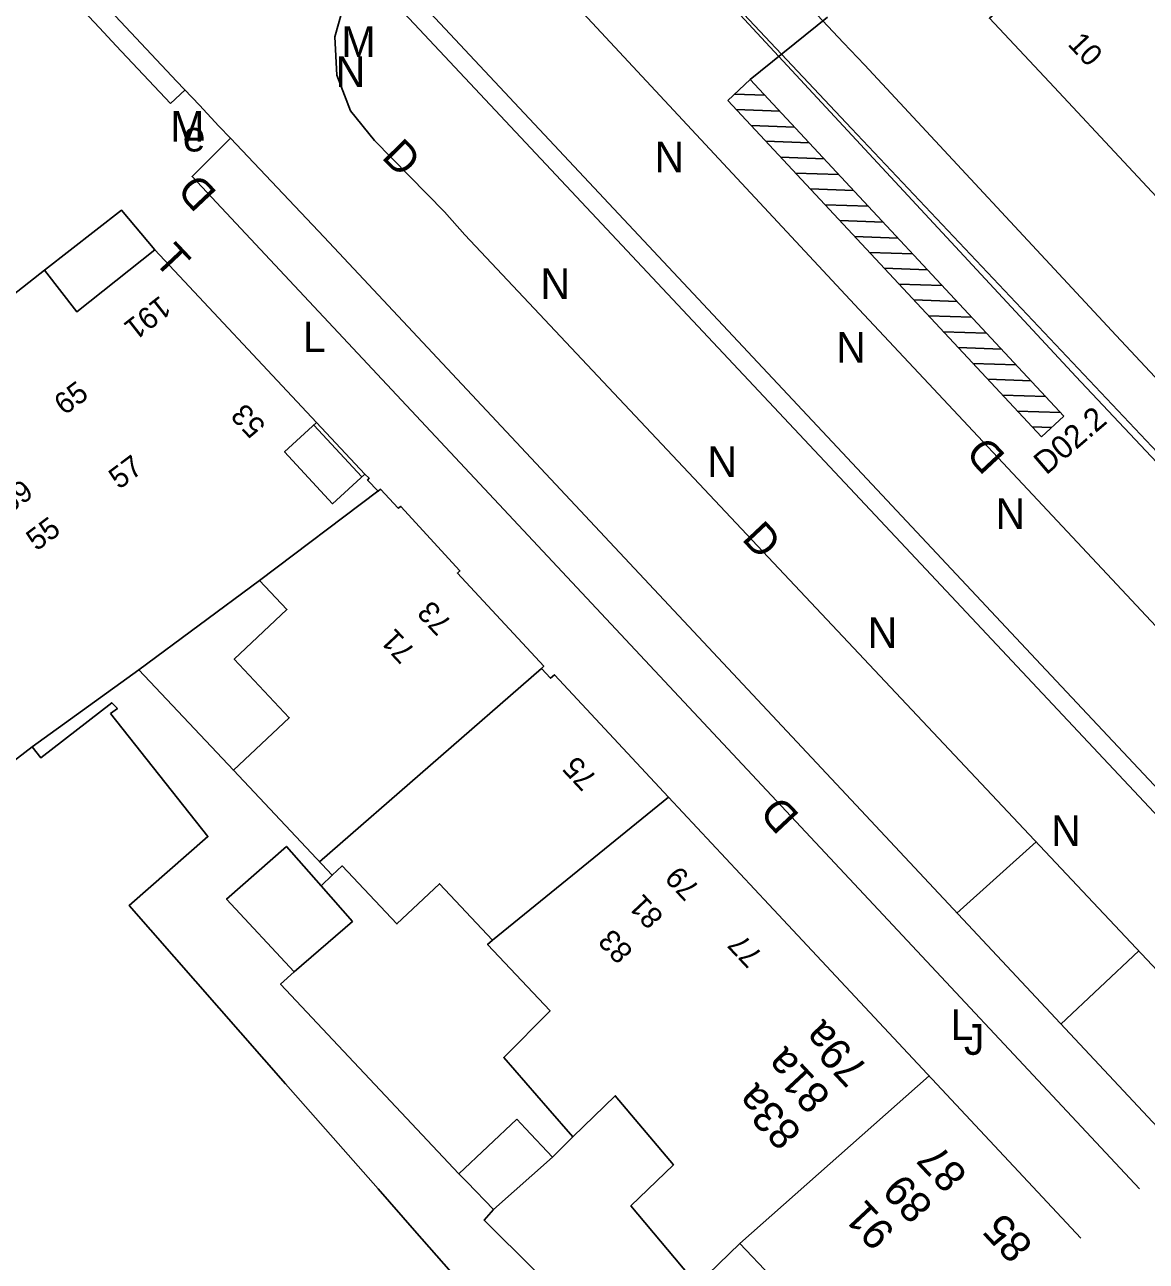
# Model space of a CAD drawing. Extents: x 81617 to 82144, y 454649 to 455150.
# Drawn here: x 81873.05 to 81909.62, y 454806.42 to 454846.75 of the extents above; entities that cross this region are included whole.
import ezdxf

# ---------------------------------------------------------------- set-up
doc = ezdxf.new("R2010")
doc.units = 0
for name, color, linetype in [('B-WE-OG-TOPOGRAFIE-G', 7, 'Continuous'), ('B-WE-VW-MARKERING-G', 7, 'Continuous'), ('N-OI-KL-VRI_KABEL_DETECTIE-G', 7, 'Continuous'), ('N-OI-KL-VRI_LUS_DETECTIE-G', 7, 'Continuous'), ('N-OI-KL-VRI_LUS_DETECTIE-T18', 7, 'Continuous')]:
    doc.layers.add(name, color=color, linetype=linetype)

msp = doc.modelspace()

# ---------------------------------------------------------------- linework, layer by layer
at = {"layer": 'B-WE-OG-TOPOGRAFIE-G'}
for p, q in [((81884.614, 454848.907), (81906.018, 454826.058)), ((81905.567, 454825.643), (81884.139, 454848.499)), ((81878.273, 454844.619), (81877.794, 454844.179)), ((81877.293, 454839.402), (81882.56, 454833.774)), ((81884.033, 454832.006), (81882.469, 454833.683)), ((81882.56, 454833.774), (81884.133, 454832.094)), ((81880.704, 454828.619), (81884.562, 454831.538)), ((81880.704, 454828.619), (81876.764, 454825.709)), ((81906.018, 454826.058), (81916.564, 454814.799)), ((81879.85, 454822.434), (81876.764, 454825.709)), ((81882.658, 454819.449), (81889.892, 454825.755)), ((81916.1, 454814.409), (81905.567, 454825.643)), ((81888.294, 454816.897), (81894.036, 454821.561)), ((81903.446, 454817.777), (81906.027, 454820.1)), ((81882.709, 454818.666), (81883.073, 454819.008)), ((81906.838, 454814.155), (81909.377, 454816.54)), ((81896.361, 454806.995), (81902.536, 454812.468)), ((81890.92, 454810.479), (81890.254, 454809.82))]:
    msp.add_line(p, q, dxfattribs=at)
for points in [[(81912.733, 454832.236), (81908.633, 454836.613), (81900.431, 454845.439), (81899.742, 454846.157), (81896.321, 454849.804), (81892.737, 454853.657), (81891.454, 454852.381)], [(81891.454, 454852.381), (81907.325, 454835.276), (81911.365, 454830.977)], [(81908.659, 454828.488), (81900.257, 454837.458), (81889.774, 454848.723), (81888.801, 454849.41), (81887.61, 454849.782), (81886.363, 454849.76), (81885.185, 454849.348), (81884.614, 454848.907)], [(81876.51, 454846.498), (81873.659, 454849.539)], [(81876.027, 454846.063), (81875.486, 454846.64), (81873.185, 454849.094)], [(81884.139, 454848.499), (81883.499, 454847.551), (81883.162, 454846.35), (81883.219, 454845.104), (81883.666, 454843.939), (81884.456, 454842.973), (81886.737, 454840.646), (81887.397, 454839.898), (81903.018, 454823.298)], [(81915.707, 454834.971), (81906.614, 454844.709), (81904.504, 454846.96), (81905.266, 454847.61)], [(81878.01, 454844.899), (81876.51, 454846.498)], [(81877.794, 454844.179), (81876.027, 454846.063)], [(81878.74, 454844.121), (81878.01, 454844.899)], [(81879.753, 454843.047), (81879.377, 454843.443), (81878.74, 454844.121)], [(81879.753, 454843.047), (81878.503, 454841.796), (81899.147, 454819.736)], [(81900.471, 454820.954), (81882.807, 454839.815), (81879.753, 454843.047)], [(81873.692, 454838.739), (81876.197, 454840.699), (81877.293, 454839.402)], [(81873.692, 454838.739), (81874.74, 454837.386), (81877.293, 454839.402)], [(81855.686, 454824.714), (81861.365, 454829.127), (81865.438, 454832.254), (81873.692, 454838.739)], [(81882.56, 454833.774), (81881.521, 454832.814), (81883.081, 454831.123), (81884.133, 454832.094)], [(81884.133, 454832.094), (81884.275, 454831.955), (81884.227, 454831.896), (81884.569, 454831.531), (81884.642, 454831.599), (81885.225, 454830.976), (81885.312, 454831.038), (81887.238, 454828.933), (81887.157, 454828.866), (81889.972, 454825.83), (81889.892, 454825.755), (81890.192, 454825.433), (81890.316, 454825.549), (81894.036, 454821.561), (81897.316, 454818.052)], [(81890.103, 454811.416), (81888.664, 454813.064), (81890.175, 454814.584), (81888.141, 454816.753), (81888.294, 454816.897), (81886.575, 454818.73), (81885.181, 454817.421), (81883.401, 454819.316), (81883.073, 454819.008), (81879.85, 454822.434), (81881.671, 454824.147), (81879.876, 454826.055), (81881.595, 454827.672), (81880.704, 454828.619)], [(81919.317, 454817.11), (81908.659, 454828.488)], [(81876.764, 454825.709), (81873.29, 454823.196), (81867.304, 454818.593), (81871.686, 454813.044), (81869.495, 454811.314), (81862.848, 454819.084), (81861.152, 454817.827), (81856.411, 454823.796), (81855.686, 454824.714)], [(81873.29, 454823.196), (81873.573, 454822.834), (81875.885, 454824.633), (81876.069, 454824.451), (81875.841, 454824.279)], [(81875.841, 454824.279), (81879.019, 454820.271), (81876.454, 454818.024), (81881.548, 454812.208), (81884.567, 454808.778), (81885.76, 454807.421)], [(81903.018, 454823.298), (81913.463, 454812.197)], [(81910.78, 454809.946), (81900.471, 454820.954)], [(81882.709, 454818.666), (81883.732, 454817.504), (81881.828, 454815.863), (81879.627, 454818.234), (81881.578, 454819.951), (81882.709, 454818.666)], [(81899.147, 454819.736), (81909.396, 454808.785)], [(81897.316, 454818.052), (81907.481, 454807.178)], [(81887.206, 454809.269), (81881.391, 454815.452), (81881.828, 454815.863)], [(81900.915, 454801.668), (81900.406, 454802.194), (81899.022, 454800.855), (81896.86, 454803.422), (81898.383, 454804.874), (81896.361, 454806.995), (81894.977, 454805.656), (81892.815, 454808.223), (81894.199, 454809.562), (81892.304, 454811.818), (81890.92, 454810.479), (81890.103, 454811.416)], [(81887.472, 454808.995), (81887.206, 454809.269), (81889.089, 454811.06)], [(81889.089, 454811.06), (81889.38, 454810.751)], [(81889.38, 454810.751), (81890.254, 454809.82), (81888.336, 454808.106), (81887.472, 454808.995)], [(81891.32, 454804.491), (81888.026, 454807.766), (81888.336, 454808.106)], [(81885.76, 454807.421), (81892.287, 454800)]]:
    msp.add_lwpolyline(points, dxfattribs=at)
at = {"layer": 'B-WE-VW-MARKERING-G'}
for p, q in [((81890.366, 454853.591), (81900.01, 454843.365)), ((81900.01, 454843.365), (81911.022, 454831.689))]:
    msp.add_line(p, q, dxfattribs=at)
at = {"layer": 'N-OI-KL-VRI_KABEL_DETECTIE-G'}
msp.add_line((81896.703, 454844.959), (81899.228, 454846.997), dxfattribs=at)
at = {"layer": 'N-OI-KL-VRI_LUS_DETECTIE-G'}
for p, q in [((81896.703, 454844.959), (81895.971, 454844.278)), ((81906.93, 454833.986), (81896.703, 454844.959)), ((81897.182, 454844.445), (81896.188, 454844.48)), ((81895.971, 454844.278), (81906.199, 454833.304)), ((81897.664, 454843.928), (81896.25, 454843.977)), ((81898.146, 454843.411), (81896.733, 454843.46)), ((81898.628, 454842.894), (81897.214, 454842.944)), ((81899.11, 454842.376), (81897.696, 454842.426)), ((81899.592, 454841.859), (81898.179, 454841.909)), ((81900.074, 454841.342), (81898.661, 454841.392)), ((81900.556, 454840.824), (81899.143, 454840.874)), ((81901.039, 454840.307), (81899.626, 454840.357)), ((81901.521, 454839.79), (81900.108, 454839.84)), ((81902.003, 454839.272), (81900.59, 454839.322)), ((81902.485, 454838.755), (81901.072, 454838.805)), ((81902.967, 454838.238), (81901.554, 454838.288)), ((81903.449, 454837.721), (81902.036, 454837.77)), ((81903.931, 454837.204), (81902.518, 454837.253)), ((81904.413, 454836.687), (81903, 454836.736)), ((81904.895, 454836.169), (81903.482, 454836.219)), ((81905.378, 454835.651), (81903.965, 454835.701)), ((81905.86, 454835.134), (81904.447, 454835.184)), ((81906.342, 454834.617), (81904.929, 454834.666)), ((81906.824, 454834.1), (81905.411, 454834.149)), ((81906.199, 454833.304), (81906.93, 454833.986)), ((81906.526, 454833.61), (81905.893, 454833.633))]:
    msp.add_line(p, q, dxfattribs=at)

# ---------------------------------------------------------------- texts
at = {"layer": 'B-WE-OG-TOPOGRAFIE-G'}
for s, p in [('M', (81883.374, 454845.694)), ('N', (81883.182, 454844.717)), ('M', (81877.794, 454842.938)), ('e', (81878.197, 454842.613)), ('N', (81893.582, 454841.934)), ('N', (81889.863, 454837.801)), ('L', (81882.115, 454836.068)), ('N', (81899.507, 454835.722)), ('N', (81895.306, 454831.995)), ('N', (81904.702, 454830.306)), ('N', (81900.533, 454826.423)), ('N', (81906.517, 454819.961)), ('L', (81903.236, 454813.633)), ('J', (81903.675, 454813.154))]:
    msp.add_text(s, height=1, dxfattribs=at).set_placement(p)
for s, height, rotation, p in [('10', 0.7, 313.0822, (81907.029, 454846.096)), ('D', 1, 314.49, (81884.652, 454842.408)), ('D', 1, 133.2643, (81879.352, 454841.265)), ('T', 1, 313.2643, (81877.221, 454839.03)), ('191', 0.7, 218.0943, (81877.46, 454837.939)), ('65', 0.7, 36.7722, (81874.341, 454833.988)), ('53', 0.7, 133.0968, (81880.939, 454833.679)), ('D', 1, 133.0494, (81905.069, 454832.694)), ('57', 0.7, 36.7722, (81876.122, 454831.573)), ('59', 0.7, 36.7722, (81872.546, 454830.774)), ('55', 0.7, 36.7722, (81873.431, 454829.562)), ('D', 1, 313.2376, (81896.4, 454829.959)), ('73', 0.7, 133.058, (81887.019, 454827.248)), ('71', 0.7, 133.058, (81885.821, 454826.333)), ('75', 0.7, 133.058, (81891.751, 454822.183)), ('D', 1, 133.0695, (81898.347, 454820.964)), ('79', 0.7, 133.058, (81895.1, 454818.599)), ('81', 0.7, 133.058, (81893.911, 454817.674)), ('83', 0.7, 133.058, (81892.918, 454816.54)), ('77', 0.7, 133.058, (81897.146, 454816.411)), ('79a', 1, 133.058, (81900.601, 454812.712)), ('81a', 1, 133.058, (81899.37, 454811.833)), ('83a', 1, 133.058, (81898.423, 454810.649)), ('87', 1, 133.058, (81903.826, 454809.261)), ('89', 1, 133.058, (81902.712, 454808.256)), ('91', 1, 133.058, (81901.468, 454807.391)), ('85', 1, 133.058, (81905.968, 454806.969))]:
    msp.add_text(s, height=height, rotation=rotation, dxfattribs=at).set_placement(p)
at = {"layer": 'N-OI-KL-VRI_LUS_DETECTIE-T18'}
msp.add_text('D02.2', height=0.75, rotation=40.5993, dxfattribs=at).set_placement((81906.355, 454832.04))

doc.saveas('drawing.dxf')
